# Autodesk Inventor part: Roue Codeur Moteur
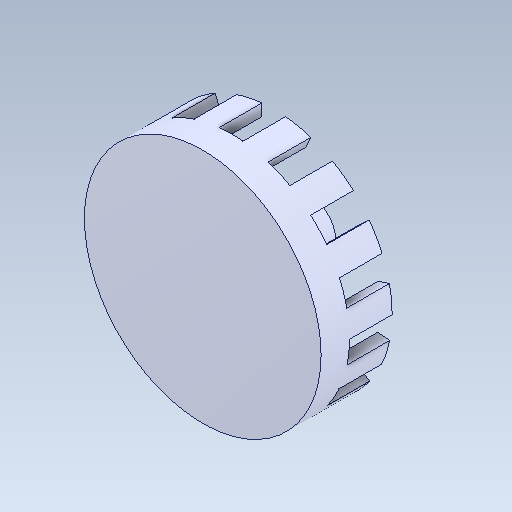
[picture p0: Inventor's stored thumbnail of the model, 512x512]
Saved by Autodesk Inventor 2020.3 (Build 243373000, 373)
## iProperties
Created: 2018-09
Part Number: Roue Codeur Moteur
Material: Générique
Document SubType Name: Modeling
Designer: ficho
Density: 1 g/cm^3
Appearance: Par défaut
Mass: 0.592374 g
Surface Area: 13.5618 cm^2
Volume: 0.592374 cm^3
Sending System: SolidWorks 2015
Last Author: expo-04
Last Saved: 2018-09-24
Author: ficho
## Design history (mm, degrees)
feature "Enlèv. mat.-Extru.1"
node "Solide1"
